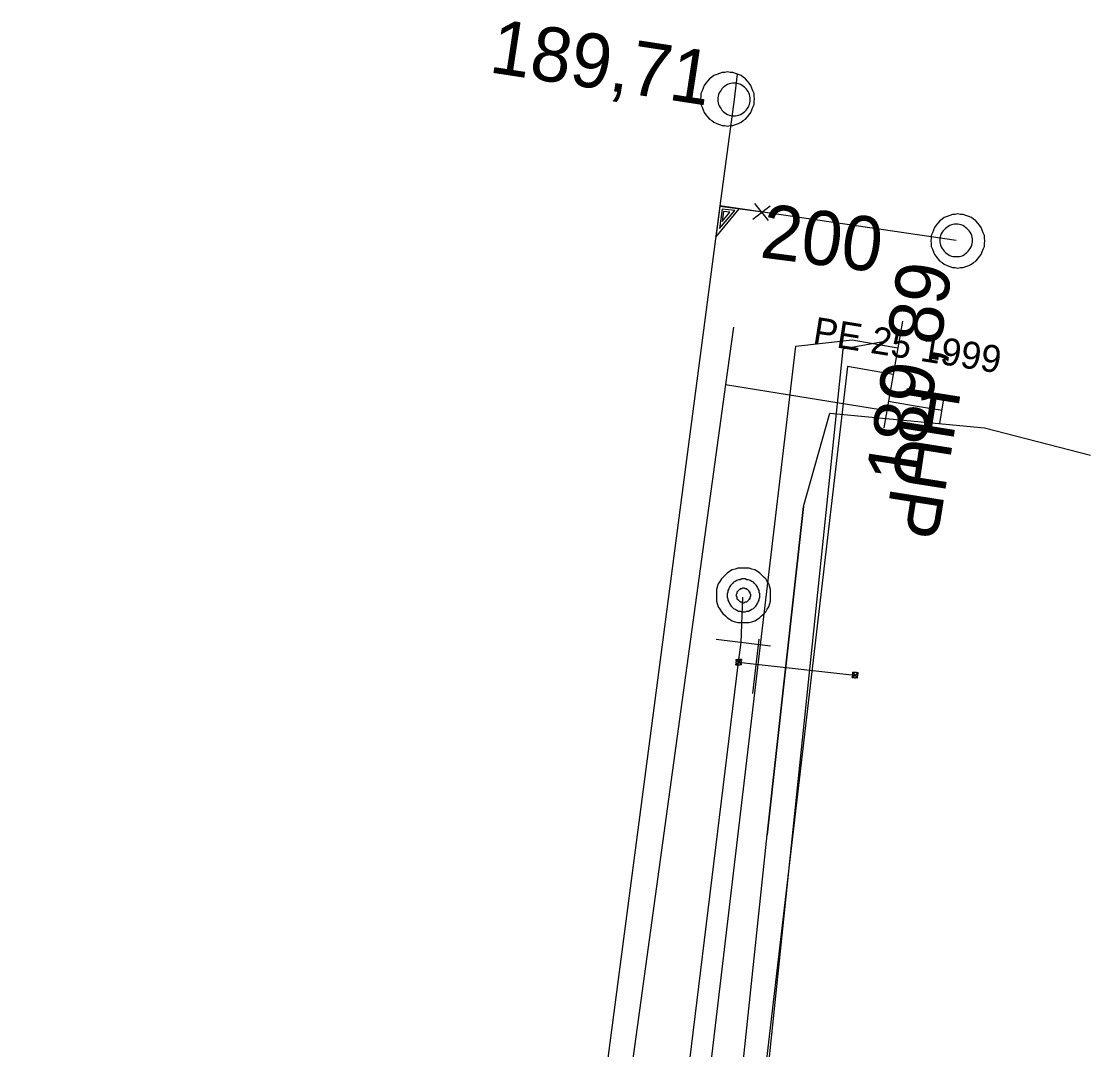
# Model space of a CAD drawing. Extents: x -746464 to -745690, y -1051581 to -1049993.
# Drawn here: x -745937.38 to -745917.65, y -1050910.77 to -1050891.8 of the extents above; entities that cross this region are included whole.
import ezdxf

# ---------------------------------------------------------------- set-up
doc = ezdxf.new("R2010")
doc.units = 0
for name, color, linetype in [('04_CETIN_sdelovaci_podzem', 7, 'Continuous'), ('48_Prazs_plynarenska_STL', 7, 'Continuous'), ('48_Prazs_plynarenska_STL_popisy', 7, 'Continuous'), ('51_PVaK_kanal_jednotna_neoverena poloha_pripojka', 7, 'Continuous'), ('51_PVaK_kanal_jednotna_overena poloha_rad', 7, 'Continuous'), ('51_PVaK_kanal_objekty', 7, 'Continuous'), ('51_PVaK_kanal_popisy', 7, 'Continuous'), ('51_PVaK_vodovod_chranicky_objekty', 7, 'Continuous'), ('51_PVaK_vodovod_NEPROVOZUJE PVK_neoverene poloha', 7, 'Continuous'), ('55_PREdi_NN', 7, 'Continuous'), ('55_PREdi_NN_pripojovaci_misto', 7, 'Continuous')]:
    doc.layers.add(name, color=color, linetype=linetype)

msp = doc.modelspace()

# ---------------------------------------------------------------- linework, layer by layer
at = {"layer": '04_CETIN_sdelovaci_podzem'}
for points in [[(-745924.55, -1050915.62), (-745923.62, -1050906.81), (-745922.95, -1050900.75), (-745922.46, -1050899.03), (-745919.61, -1050899.3), (-745917.65, -1050899.8)], [(-745922.95, -1050900.75), (-745923.62, -1050906.81)]]:
    msp.add_lwpolyline(points, dxfattribs=at)
at = {"layer": '48_Prazs_plynarenska_STL'}
for points in [[(-745924.24, -1050897.439), (-745924.39, -1050898.5), (-745926.58, -1050914.43), (-745928.11, -1050927.89), (-745929.03, -1050935.56), (-745929.042, -1050935.678), (-745929.45, -1050939.54), (-745929.68, -1050942.17), (-745930.6, -1050952.07), (-745931.04, -1050958.72), (-745931.04, -1050959.41), (-745931.16, -1050963.77), (-745931.63, -1050972.21), (-745932.22, -1050976.26), (-745932.83, -1050980.22), (-745934.11, -1050987.61), (-745935.84, -1050998.78), (-745937.38, -1051010.18), (-745934.03, -1051011.36), (-745934.04, -1051011.96)], [(-745924.39, -1050898.5), (-745921.528, -1050898.958)]]:
    msp.add_lwpolyline(points, dxfattribs=at)
at = {"layer": '51_PVaK_kanal_jednotna_neoverena poloha_pripojka'}
msp.add_line((-745920.13, -1050895.84), (-745924.489, -1050895.205), dxfattribs=at)
at = {"layer": '51_PVaK_kanal_jednotna_overena poloha_rad'}
msp.add_line((-745924.17, -1050892.77), (-745924.23, -1050893.24), dxfattribs=at)
msp.add_lwpolyline([(-745924.23, -1050893.24), (-745924.489, -1050895.205), (-745926.679, -1050911.862), (-745928.844, -1050928.32), (-745930.07, -1050937.64)], dxfattribs=at)
at = {"layer": '51_PVaK_kanal_objekty'}
for p, q in [((-745923.596, -1050895.474), (-745923.843, -1050895.161)), ((-745923.885, -1050895.448), (-745923.564, -1050895.204))]:
    msp.add_line(p, q, dxfattribs=at)
for points in [[(-745923.85, -1050893.23), (-745923.86, -1050893.18), (-745923.86, -1050893.13), (-745923.88, -1050893.08), (-745923.9, -1050893.03), (-745923.92, -1050892.98), (-745923.95, -1050892.94), (-745923.98, -1050892.9), (-745924.02, -1050892.86), (-745924.06, -1050892.83), (-745924.1, -1050892.8), (-745924.15, -1050892.78), (-745924.2, -1050892.76), (-745924.25, -1050892.74), (-745924.3, -1050892.74), (-745924.35, -1050892.73), (-745924.4, -1050892.74), (-745924.45, -1050892.74), (-745924.5, -1050892.76), (-745924.55, -1050892.78), (-745924.6, -1050892.8), (-745924.64, -1050892.83), (-745924.68, -1050892.86), (-745924.72, -1050892.9), (-745924.75, -1050892.94), (-745924.78, -1050892.98), (-745924.8, -1050893.03), (-745924.82, -1050893.08), (-745924.84, -1050893.13), (-745924.84, -1050893.18), (-745924.85, -1050893.23), (-745924.84, -1050893.28), (-745924.84, -1050893.33), (-745924.82, -1050893.38), (-745924.8, -1050893.43), (-745924.78, -1050893.48), (-745924.75, -1050893.52), (-745924.72, -1050893.56), (-745924.68, -1050893.6), (-745924.64, -1050893.63), (-745924.6, -1050893.66), (-745924.55, -1050893.68), (-745924.5, -1050893.7), (-745924.45, -1050893.72), (-745924.4, -1050893.72), (-745924.35, -1050893.73), (-745924.3, -1050893.72), (-745924.25, -1050893.72), (-745924.2, -1050893.7), (-745924.15, -1050893.68), (-745924.1, -1050893.66), (-745924.06, -1050893.63), (-745924.02, -1050893.6), (-745923.98, -1050893.56), (-745923.95, -1050893.52), (-745923.92, -1050893.48), (-745923.9, -1050893.43), (-745923.88, -1050893.38), (-745923.86, -1050893.33), (-745923.86, -1050893.28), (-745923.85, -1050893.23)], [(-745923.93, -1050893.24), (-745923.93, -1050893.21), (-745923.936, -1050893.18), (-745923.942, -1050893.15), (-745923.954, -1050893.12), (-745923.972, -1050893.09), (-745923.99, -1050893.066), (-745924.008, -1050893.042), (-745924.032, -1050893.018), (-745924.056, -1050893), (-745924.08, -1050892.982), (-745924.11, -1050892.964), (-745924.14, -1050892.952), (-745924.17, -1050892.946), (-745924.2, -1050892.94), (-745924.23, -1050892.94), (-745924.26, -1050892.94), (-745924.29, -1050892.946), (-745924.32, -1050892.952), (-745924.35, -1050892.964), (-745924.38, -1050892.982), (-745924.404, -1050893), (-745924.428, -1050893.018), (-745924.452, -1050893.042), (-745924.47, -1050893.066), (-745924.488, -1050893.09), (-745924.506, -1050893.12), (-745924.518, -1050893.15), (-745924.524, -1050893.18), (-745924.53, -1050893.21), (-745924.53, -1050893.24), (-745924.53, -1050893.27), (-745924.524, -1050893.3), (-745924.518, -1050893.33), (-745924.506, -1050893.36), (-745924.488, -1050893.39), (-745924.47, -1050893.414), (-745924.452, -1050893.438), (-745924.428, -1050893.462), (-745924.404, -1050893.48), (-745924.38, -1050893.498), (-745924.35, -1050893.516), (-745924.32, -1050893.528), (-745924.29, -1050893.534), (-745924.26, -1050893.54), (-745924.23, -1050893.54), (-745924.2, -1050893.54), (-745924.17, -1050893.534), (-745924.14, -1050893.528), (-745924.11, -1050893.516), (-745924.08, -1050893.498), (-745924.056, -1050893.48), (-745924.032, -1050893.462), (-745924.008, -1050893.438), (-745923.99, -1050893.414), (-745923.972, -1050893.39), (-745923.954, -1050893.36), (-745923.942, -1050893.33), (-745923.936, -1050893.3), (-745923.93, -1050893.27), (-745923.93, -1050893.24)], [(-745923.698, -1050895.317), (-745924.49, -1050895.213), (-745924.564, -1050895.778), (-745924.133, -1050895.26)], [(-745924.218, -1050895.291), (-745924.448, -1050895.261), (-745924.496, -1050895.621), (-745924.217, -1050895.287)], [(-745924.306, -1050895.322), (-745924.422, -1050895.306), (-745924.446, -1050895.492), (-745924.306, -1050895.318)], [(-745919.6, -1050895.85), (-745919.61, -1050895.8), (-745919.61, -1050895.75), (-745919.63, -1050895.7), (-745919.65, -1050895.65), (-745919.67, -1050895.6), (-745919.7, -1050895.56), (-745919.73, -1050895.52), (-745919.77, -1050895.48), (-745919.81, -1050895.45), (-745919.85, -1050895.42), (-745919.9, -1050895.4), (-745919.95, -1050895.38), (-745920, -1050895.36), (-745920.05, -1050895.36), (-745920.1, -1050895.35), (-745920.15, -1050895.36), (-745920.2, -1050895.36), (-745920.25, -1050895.38), (-745920.3, -1050895.4), (-745920.35, -1050895.42), (-745920.39, -1050895.45), (-745920.43, -1050895.48), (-745920.47, -1050895.52), (-745920.5, -1050895.56), (-745920.53, -1050895.6), (-745920.55, -1050895.65), (-745920.57, -1050895.7), (-745920.59, -1050895.75), (-745920.59, -1050895.8), (-745920.6, -1050895.85), (-745920.59, -1050895.9), (-745920.59, -1050895.95), (-745920.57, -1050896), (-745920.55, -1050896.05), (-745920.53, -1050896.1), (-745920.5, -1050896.14), (-745920.47, -1050896.18), (-745920.43, -1050896.22), (-745920.39, -1050896.25), (-745920.35, -1050896.28), (-745920.3, -1050896.3), (-745920.25, -1050896.32), (-745920.2, -1050896.34), (-745920.15, -1050896.34), (-745920.1, -1050896.35), (-745920.05, -1050896.34), (-745920, -1050896.34), (-745919.95, -1050896.32), (-745919.9, -1050896.3), (-745919.85, -1050896.28), (-745919.81, -1050896.25), (-745919.77, -1050896.22), (-745919.73, -1050896.18), (-745919.7, -1050896.14), (-745919.67, -1050896.1), (-745919.65, -1050896.05), (-745919.63, -1050896), (-745919.61, -1050895.95), (-745919.61, -1050895.9), (-745919.6, -1050895.85)], [(-745919.83, -1050895.84), (-745919.83, -1050895.81), (-745919.836, -1050895.78), (-745919.842, -1050895.75), (-745919.854, -1050895.72), (-745919.872, -1050895.69), (-745919.89, -1050895.666), (-745919.908, -1050895.642), (-745919.932, -1050895.618), (-745919.956, -1050895.6), (-745919.98, -1050895.582), (-745920.01, -1050895.564), (-745920.04, -1050895.552), (-745920.07, -1050895.546), (-745920.1, -1050895.54), (-745920.13, -1050895.54), (-745920.16, -1050895.54), (-745920.19, -1050895.546), (-745920.22, -1050895.552), (-745920.25, -1050895.564), (-745920.28, -1050895.582), (-745920.304, -1050895.6), (-745920.328, -1050895.618), (-745920.352, -1050895.642), (-745920.37, -1050895.666), (-745920.388, -1050895.69), (-745920.406, -1050895.72), (-745920.418, -1050895.75), (-745920.424, -1050895.78), (-745920.43, -1050895.81), (-745920.43, -1050895.84), (-745920.43, -1050895.87), (-745920.424, -1050895.9), (-745920.418, -1050895.93), (-745920.406, -1050895.96), (-745920.388, -1050895.99), (-745920.37, -1050896.014), (-745920.352, -1050896.038), (-745920.328, -1050896.062), (-745920.304, -1050896.08), (-745920.28, -1050896.098), (-745920.25, -1050896.116), (-745920.22, -1050896.128), (-745920.19, -1050896.134), (-745920.16, -1050896.14), (-745920.13, -1050896.14), (-745920.1, -1050896.14), (-745920.07, -1050896.134), (-745920.04, -1050896.128), (-745920.01, -1050896.116), (-745919.98, -1050896.098), (-745919.956, -1050896.08), (-745919.932, -1050896.062), (-745919.908, -1050896.038), (-745919.89, -1050896.014), (-745919.872, -1050895.99), (-745919.854, -1050895.96), (-745919.842, -1050895.93), (-745919.836, -1050895.9), (-745919.83, -1050895.87), (-745919.83, -1050895.84)]]:
    msp.add_lwpolyline(points, dxfattribs=at)
at = {"layer": '51_PVaK_vodovod_chranicky_objekty'}
for p, q in [((-745923.56, -1050903.327), (-745924.56, -1050903.203)), ((-745923.88, -1050904.2), (-745923.769, -1050903.2)), ((-745924.194, -1050903.673), (-745924.094, -1050903.573)), ((-745924.194, -1050903.573), (-745924.094, -1050903.673)), ((-745924.194, -1050903.573), (-745924.194, -1050903.593)), ((-745924.194, -1050903.573), (-745924.174, -1050903.573)), ((-745924.094, -1050903.573), (-745924.114, -1050903.573)), ((-745924.094, -1050903.573), (-745924.094, -1050903.593)), ((-745924.194, -1050903.673), (-745924.194, -1050903.653)), ((-745924.194, -1050903.673), (-745924.174, -1050903.673)), ((-745924.094, -1050903.673), (-745924.114, -1050903.673)), ((-745924.094, -1050903.673), (-745924.094, -1050903.653)), ((-745922.052, -1050903.904), (-745921.942, -1050903.816)), ((-745922.041, -1050903.805), (-745922.044, -1050903.825)), ((-745922.041, -1050903.805), (-745921.953, -1050903.915)), ((-745922.041, -1050903.805), (-745922.021, -1050903.807)), ((-745921.942, -1050903.816), (-745921.962, -1050903.814)), ((-745921.942, -1050903.816), (-745921.944, -1050903.836)), ((-745922.052, -1050903.904), (-745922.05, -1050903.884)), ((-745922.052, -1050903.904), (-745922.032, -1050903.906)), ((-745921.953, -1050903.915), (-745921.973, -1050903.913)), ((-745921.953, -1050903.915), (-745921.951, -1050903.895))]:
    msp.add_line(p, q, dxfattribs=at)
for points in [[(-745923.555, -1050902.39), (-745923.555, -1050902.344), (-745923.555, -1050902.284), (-745923.57, -1050902.238), (-745923.585, -1050902.178), (-745923.616, -1050902.132), (-745923.646, -1050902.087), (-745923.676, -1050902.057), (-745923.722, -1050902.011), (-745923.752, -1050901.981), (-745923.797, -1050901.951), (-745923.843, -1050901.92), (-745923.903, -1050901.905), (-745923.949, -1050901.89), (-745924.009, -1050901.89), (-745924.055, -1050901.89), (-745924.116, -1050901.89), (-745924.161, -1050901.89), (-745924.206, -1050901.905), (-745924.267, -1050901.92), (-745924.313, -1050901.951), (-745924.358, -1050901.981), (-745924.388, -1050902.011), (-745924.434, -1050902.057), (-745924.464, -1050902.087), (-745924.494, -1050902.132), (-745924.525, -1050902.178), (-745924.54, -1050902.238), (-745924.555, -1050902.284), (-745924.555, -1050902.344), (-745924.555, -1050902.39), (-745924.555, -1050902.451), (-745924.555, -1050902.496), (-745924.54, -1050902.541), (-745924.525, -1050902.602), (-745924.494, -1050902.647), (-745924.464, -1050902.693), (-745924.434, -1050902.723), (-745924.388, -1050902.769), (-745924.358, -1050902.799), (-745924.313, -1050902.829), (-745924.267, -1050902.86), (-745924.206, -1050902.875), (-745924.161, -1050902.89), (-745924.116, -1050902.89), (-745924.055, -1050902.89), (-745924.009, -1050902.89), (-745923.949, -1050902.89), (-745923.903, -1050902.875), (-745923.843, -1050902.86), (-745923.797, -1050902.829), (-745923.752, -1050902.799), (-745923.722, -1050902.769), (-745923.676, -1050902.723), (-745923.646, -1050902.693), (-745923.616, -1050902.647), (-745923.585, -1050902.602), (-745923.57, -1050902.541), (-745923.555, -1050902.496), (-745923.555, -1050902.451), (-745923.555, -1050902.39)], [(-745923.752, -1050902.39), (-745923.752, -1050902.36), (-745923.767, -1050902.329), (-745923.767, -1050902.299), (-745923.782, -1050902.269), (-745923.797, -1050902.238), (-745923.813, -1050902.208), (-745923.828, -1050902.193), (-745923.858, -1050902.163), (-745923.873, -1050902.147), (-745923.903, -1050902.132), (-745923.934, -1050902.117), (-745923.964, -1050902.102), (-745923.994, -1050902.102), (-745924.025, -1050902.087), (-745924.055, -1050902.087), (-745924.085, -1050902.087), (-745924.116, -1050902.102), (-745924.146, -1050902.102), (-745924.176, -1050902.117), (-745924.206, -1050902.132), (-745924.237, -1050902.147), (-745924.252, -1050902.163), (-745924.282, -1050902.193), (-745924.297, -1050902.208), (-745924.313, -1050902.238), (-745924.328, -1050902.269), (-745924.343, -1050902.299), (-745924.343, -1050902.329), (-745924.358, -1050902.36), (-745924.358, -1050902.39), (-745924.358, -1050902.42), (-745924.343, -1050902.451), (-745924.343, -1050902.481), (-745924.328, -1050902.511), (-745924.313, -1050902.541), (-745924.297, -1050902.572), (-745924.282, -1050902.587), (-745924.252, -1050902.617), (-745924.237, -1050902.632), (-745924.206, -1050902.647), (-745924.176, -1050902.663), (-745924.146, -1050902.678), (-745924.116, -1050902.678), (-745924.085, -1050902.693), (-745924.055, -1050902.693), (-745924.025, -1050902.693), (-745923.994, -1050902.678), (-745923.964, -1050902.678), (-745923.934, -1050902.663), (-745923.903, -1050902.647), (-745923.873, -1050902.632), (-745923.858, -1050902.617), (-745923.828, -1050902.587), (-745923.813, -1050902.572), (-745923.797, -1050902.541), (-745923.782, -1050902.511), (-745923.767, -1050902.481), (-745923.767, -1050902.451), (-745923.752, -1050902.42), (-745923.752, -1050902.39)], [(-745923.919, -1050902.39), (-745923.919, -1050902.375), (-745923.934, -1050902.36), (-745923.934, -1050902.344), (-745923.934, -1050902.329), (-745923.949, -1050902.329), (-745923.949, -1050902.314), (-745923.964, -1050902.299), (-745923.979, -1050902.284), (-745923.994, -1050902.284), (-745923.994, -1050902.269), (-745924.009, -1050902.269), (-745924.025, -1050902.269), (-745924.04, -1050902.254), (-745924.055, -1050902.254), (-745924.07, -1050902.254), (-745924.085, -1050902.269), (-745924.1, -1050902.269), (-745924.116, -1050902.269), (-745924.116, -1050902.284), (-745924.131, -1050902.284), (-745924.146, -1050902.299), (-745924.161, -1050902.314), (-745924.176, -1050902.329), (-745924.176, -1050902.344), (-745924.176, -1050902.36), (-745924.191, -1050902.375), (-745924.191, -1050902.39), (-745924.191, -1050902.405), (-745924.176, -1050902.42), (-745924.176, -1050902.435), (-745924.176, -1050902.451), (-745924.161, -1050902.466), (-745924.146, -1050902.481), (-745924.131, -1050902.496), (-745924.116, -1050902.511), (-745924.1, -1050902.511), (-745924.085, -1050902.511), (-745924.07, -1050902.526), (-745924.055, -1050902.526), (-745924.04, -1050902.526), (-745924.025, -1050902.511), (-745924.009, -1050902.511), (-745923.994, -1050902.511), (-745923.979, -1050902.496), (-745923.964, -1050902.481), (-745923.949, -1050902.466), (-745923.949, -1050902.451), (-745923.934, -1050902.451), (-745923.934, -1050902.435), (-745923.934, -1050902.42), (-745923.919, -1050902.405), (-745923.919, -1050902.39)], [(-745924.094, -1050903.623), (-745924.094, -1050903.618), (-745924.095, -1050903.613), (-745924.096, -1050903.608), (-745924.098, -1050903.603), (-745924.101, -1050903.598), (-745924.104, -1050903.594), (-745924.107, -1050903.59), (-745924.111, -1050903.586), (-745924.115, -1050903.583), (-745924.119, -1050903.58), (-745924.124, -1050903.577), (-745924.129, -1050903.575), (-745924.134, -1050903.574), (-745924.139, -1050903.573), (-745924.144, -1050903.573), (-745924.149, -1050903.573), (-745924.154, -1050903.574), (-745924.159, -1050903.575), (-745924.164, -1050903.577), (-745924.169, -1050903.58), (-745924.173, -1050903.583), (-745924.177, -1050903.586), (-745924.181, -1050903.59), (-745924.184, -1050903.594), (-745924.187, -1050903.598), (-745924.19, -1050903.603), (-745924.192, -1050903.608), (-745924.193, -1050903.613), (-745924.194, -1050903.618), (-745924.194, -1050903.623), (-745924.194, -1050903.628), (-745924.193, -1050903.633), (-745924.192, -1050903.638), (-745924.19, -1050903.643), (-745924.187, -1050903.648), (-745924.184, -1050903.652), (-745924.181, -1050903.656), (-745924.177, -1050903.66), (-745924.173, -1050903.663), (-745924.169, -1050903.666), (-745924.164, -1050903.669), (-745924.159, -1050903.671), (-745924.154, -1050903.672), (-745924.149, -1050903.673), (-745924.144, -1050903.673), (-745924.139, -1050903.673), (-745924.134, -1050903.672), (-745924.129, -1050903.671), (-745924.124, -1050903.669), (-745924.119, -1050903.666), (-745924.115, -1050903.663), (-745924.111, -1050903.66), (-745924.107, -1050903.656), (-745924.104, -1050903.652), (-745924.101, -1050903.648), (-745924.098, -1050903.643), (-745924.096, -1050903.638), (-745924.095, -1050903.633), (-745924.094, -1050903.628), (-745924.094, -1050903.623)], [(-745921.947, -1050903.865), (-745921.947, -1050903.86), (-745921.947, -1050903.855), (-745921.948, -1050903.85), (-745921.949, -1050903.845), (-745921.952, -1050903.84), (-745921.954, -1050903.835), (-745921.957, -1050903.831), (-745921.96, -1050903.827), (-745921.964, -1050903.823), (-745921.968, -1050903.82), (-745921.972, -1050903.816), (-745921.977, -1050903.814), (-745921.982, -1050903.812), (-745921.987, -1050903.811), (-745921.992, -1050903.81), (-745921.997, -1050903.81), (-745922.002, -1050903.81), (-745922.007, -1050903.811), (-745922.012, -1050903.812), (-745922.017, -1050903.814), (-745922.022, -1050903.817), (-745922.026, -1050903.82), (-745922.03, -1050903.823), (-745922.034, -1050903.827), (-745922.037, -1050903.83), (-745922.041, -1050903.835), (-745922.043, -1050903.84), (-745922.045, -1050903.845), (-745922.046, -1050903.849), (-745922.047, -1050903.854), (-745922.047, -1050903.859), (-745922.047, -1050903.864), (-745922.046, -1050903.87), (-745922.045, -1050903.875), (-745922.043, -1050903.88), (-745922.04, -1050903.884), (-745922.037, -1050903.889), (-745922.034, -1050903.893), (-745922.03, -1050903.896), (-745922.027, -1050903.9), (-745922.022, -1050903.903), (-745922.017, -1050903.906), (-745922.012, -1050903.908), (-745922.008, -1050903.909), (-745922.003, -1050903.91), (-745921.998, -1050903.91), (-745921.993, -1050903.91), (-745921.987, -1050903.909), (-745921.982, -1050903.908), (-745921.977, -1050903.905), (-745921.973, -1050903.903), (-745921.968, -1050903.9), (-745921.964, -1050903.897), (-745921.961, -1050903.893), (-745921.957, -1050903.889), (-745921.954, -1050903.885), (-745921.951, -1050903.88), (-745921.949, -1050903.875), (-745921.948, -1050903.87), (-745921.947, -1050903.865)]]:
    msp.add_lwpolyline(points, dxfattribs=at)
at = {"layer": '51_PVaK_vodovod_NEPROVOZUJE PVK_neoverene poloha'}
for p, q in [((-745924.1, -1050903.26), (-745924.07, -1050902.42)), ((-745924.145, -1050903.624), (-745924.1, -1050903.26)), ((-745924.145, -1050903.624), (-745923.82, -1050903.66)), ((-745923.82, -1050903.66), (-745921.998, -1050903.861))]:
    msp.add_line(p, q, dxfattribs=at)
msp.add_lwpolyline([(-745930.78, -1050957.82), (-745928.771, -1050941.412), (-745926.792, -1050925.245), (-745924.145, -1050903.624)], dxfattribs=at)
at = {"layer": '55_PREdi_NN'}
for points in [[(-745921.119, -1050897.33), (-745921.205, -1050897.823), (-745921.291, -1050898.315), (-745921.377, -1050898.808), (-745921.463, -1050899.3)], [(-745925.944, -1050974.322), (-745925.439, -1050973.802), (-745929.534, -1050967.465), (-745931.161, -1050966.035), (-745923.087, -1050897.794), (-745922.052, -1050897.675), (-745921.205, -1050897.823)], [(-745921.446, -1050897.706), (-745922.223, -1050897.847), (-745924.087, -1050915.752), (-745925.959, -1050931.626), (-745928.205, -1050950.605)], [(-745921.291, -1050898.315), (-745922.138, -1050898.167), (-745923.73, -1050911.79), (-745922.848, -1050911.893)], [(-745921.377, -1050898.808), (-745920.885, -1050898.894)]]:
    msp.add_lwpolyline(points, dxfattribs=at)
at = {"layer": '55_PREdi_NN_pripojovaci_misto'}
for p, q in [((-745920.885, -1050898.894), (-745920.391, -1050898.972)), ((-745920.43, -1050899.219), (-745920.352, -1050898.725))]:
    msp.add_line(p, q, dxfattribs=at)

# ---------------------------------------------------------------- texts
at = {"layer": '48_Prazs_plynarenska_STL_popisy'}
for s, height, rotation, p in [('PE 25 1999', 0.5, 350.9082, (-745922.794, -1050897.743)), ('HUP', 1, 261, (-745921.028, -1050898.458))]:
    msp.add_text(s, height=height, rotation=rotation, dxfattribs=at).set_placement(p)
at = {"layer": '51_PVaK_kanal_popisy'}
for s, rotation, p in [('189,71', 351.3045, (-745928.77, -1050892.735)), ('200', 352.7107, (-745923.771, -1050896.15)), ('189,89', 81.3495, (-745920.815, -1050900.375))]:
    msp.add_text(s, height=1, rotation=rotation, dxfattribs=at).set_placement(p)

doc.saveas('drawing.dxf')
